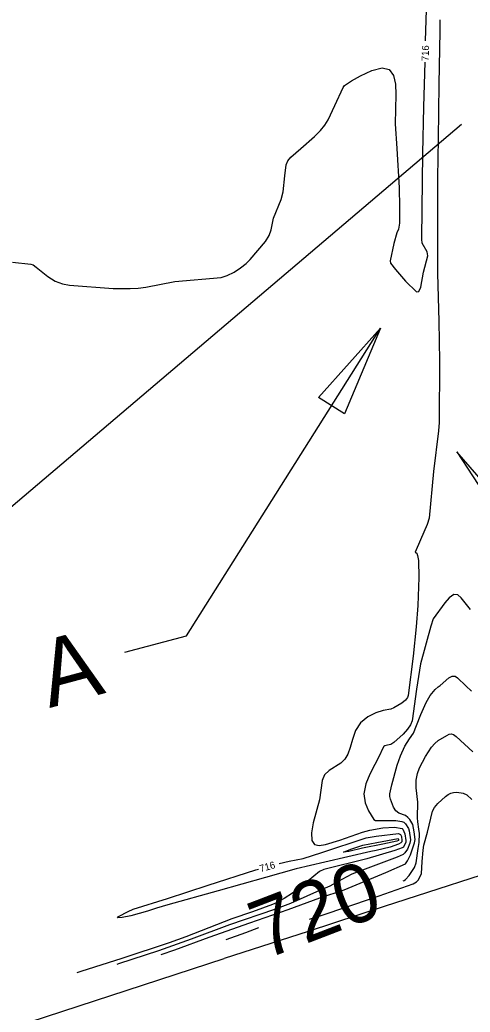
# Model space of a CAD drawing. Extents: x -361782338 to 28259792, y -263199453 to 8342113.
# Drawn here: x 1403593 to 1403847, y 576353 to 576912 of the extents above; entities that cross this region are included whole.
import ezdxf

# ---------------------------------------------------------------- set-up
doc = ezdxf.new("R2010")
doc.units = 0
for name, color, linetype in [('DT_X_Contour_Minor', 7, 'Continuous'), ('Level 14', 7, 'Continuous'), ('Level 19', 7, 'Continuous'), ('Level 40', 7, 'Continuous')]:
    doc.layers.add(name, color=color, linetype=linetype)

msp = doc.modelspace()

# ---------------------------------------------------------------- linework, layer by layer
at = {"layer": 'DT_X_Contour_Minor'}
for points in [[(1403821.78, 576911.42), (1403822.06, 576923.26)], [(1403829.55, 576911.53), (1403829.49, 576905.1), (1403829.01, 576875.26), (1403828.59, 576844.44), (1403828.19, 576822.78), (1403828.15, 576791.45), (1403828.18, 576768.59), (1403828.92, 576741.81), (1403829.26, 576719.37), (1403829.07, 576684.77), (1403828.78, 576680.05), (1403825.88, 576657.2), (1403823.4, 576630.94), (1403822.35, 576627.29), (1403818.6, 576618.64), (1403815.5, 576611.83), (1403816.42, 576611.11), (1403816.98, 576609.82), (1403817.41, 576607.14), (1403817.57, 576597.56), (1403817.02, 576581.73), (1403816.16, 576569.64), (1403814.48, 576553.18), (1403811.65, 576531.01), (1403811.17, 576529.81), (1403810.04, 576528.37), (1403808.09, 576526.73), (1403803.54, 576523.99), (1403801.86, 576523.41), (1403797.46, 576522.48), (1403793.45, 576521.21), (1403788.84, 576519.02), (1403784.75, 576515.71), (1403781.99, 576511.26), (1403780.27, 576506.31), (1403779.01, 576501.66), (1403777.69, 576497.95), (1403775.97, 576495.09), (1403773.58, 576492.83), (1403767.13, 576488.86), (1403764.5, 576486.35), (1403763.11, 576483.09), (1403761.57, 576472.34), (1403758.03, 576459.23), (1403757.14, 576453.77), (1403757.24, 576449.43), (1403758.74, 576447.15), (1403761.43, 576446.6), (1403764.93, 576447.14), (1403773.14, 576449.58), (1403785.89, 576454.09), (1403789.93, 576455.23), (1403797.25, 576456.44), (1403804, 576456.78), (1403808.3, 576456.14), (1403808.69, 576455.67), (1403809.72, 576453.15), (1403810.37, 576449.42), (1403810.29, 576448.36), (1403808.97, 576445.6), (1403808.28, 576445.18), (1403804.02, 576443.74), (1403788.36, 576439.08), (1403764.06, 576433.08), (1403761.63, 576431.9), (1403755.15, 576426.7), (1403746.41, 576419.75), (1403741.67, 576416.76), (1403739.7, 576415.55), (1403738.2, 576414.63), (1403735.11, 576413.24), (1403723.82, 576409.21), (1403712.18, 576405.2), (1403686.33, 576395.18), (1403676.92, 576391.74), (1403650.21, 576382.96), (1403626.98, 576375.57), (1403624.87, 576374.87)], [(1403821.46, 576899.62), (1403821.75, 576911.41)], [(1403742.82, 576829.82), (1403743.76, 576832.12), (1403745.44, 576834.22), (1403751.06, 576839.03), (1403758.72, 576845.78), (1403762.13, 576849.19), (1403764.63, 576852.23), (1403766.54, 576855.27), (1403770.31, 576863.26), (1403774.95, 576873.37), (1403775.8, 576874.59), (1403776.81, 576875.38), (1403779.62, 576877.17), (1403784.76, 576880.08), (1403791.05, 576883.01), (1403796.87, 576884.51), (1403800.94, 576883.5), (1403803.32, 576880.25), (1403804.44, 576875.39), (1403804.7, 576869.56), (1403804.24, 576852.97), (1403805.23, 576839.06), (1403806.58, 576816.91), (1403806.81, 576806), (1403806.67, 576797.08), (1403806.23, 576793.73), (1403805.2, 576791.5), (1403803.62, 576785.57), (1403801.45, 576775.81), (1403801.66, 576774.56), (1403804.4, 576771.02), (1403810.18, 576764.42), (1403816.23, 576758.33), (1403817.72, 576758.48), (1403818.71, 576761.02), (1403820.26, 576769.5), (1403822.8, 576778.71), (1403822.28, 576780.83), (1403819.55, 576785.8), (1403819.31, 576788.06), (1403819.5, 576805.17), (1403819.86, 576836.27), (1403820.46, 576862.46), (1403821.16, 576887.62)], [(1403588.46, 576775), (1403598.89, 576774.01), (1403600.13, 576773.56), (1403601.9, 576772.26), (1403608.4, 576766.9), (1403612.49, 576764.36), (1403616.65, 576762.84), (1403620.75, 576762.13), (1403645.35, 576760.32), (1403654.8, 576760.23), (1403659.43, 576760.5), (1403663.78, 576761.03), (1403680.13, 576764.11), (1403706.17, 576766.47), (1403709.63, 576767.53), (1403713.42, 576769.44), (1403717.14, 576771.88), (1403720.27, 576774.37), (1403722.5, 576776.57), (1403731.21, 576786.75), (1403733.27, 576790.02), (1403734.37, 576793.33), (1403735.62, 576799.87), (1403740, 576810.3), (1403741.05, 576814.74), (1403742.09, 576823.61), (1403742.82, 576829.82)], [(1403846.72, 576579.41), (1403841.51, 576586.1), (1403839.62, 576587.67), (1403837.39, 576587.86), (1403834.82, 576586.11), (1403832.31, 576583.29), (1403825.75, 576574.28), (1403824.41, 576570.11), (1403818.51, 576548.85), (1403816.33, 576534.65), (1403813.79, 576516.72), (1403812.92, 576514.5), (1403811.33, 576512.04), (1403808.86, 576509.27), (1403803.5, 576504.52), (1403801.79, 576503.47), (1403799.92, 576503.1), (1403798.42, 576502.69), (1403797.83, 576502.22), (1403797.05, 576500.63), (1403795.67, 576497.56), (1403789.98, 576486.76), (1403787.76, 576481.29), (1403786.72, 576475.68), (1403787.46, 576470.49), (1403789.27, 576466.13), (1403792.25, 576461.27), (1403793.12, 576460.63), (1403796.7, 576460.59), (1403804.62, 576460.57), (1403808.03, 576460.1), (1403809.23, 576459.59), (1403810.21, 576458.75), (1403811.79, 576456.21), (1403812.18, 576454.87), (1403812.9, 576449.71), (1403812.51, 576447.88), (1403811.22, 576444.55), (1403809.71, 576442.34), (1403808.74, 576441.53), (1403805.36, 576440.04), (1403779.78, 576430.43), (1403774.27, 576427.4), (1403767.4, 576423.56), (1403759.98, 576420.38), (1403745.22, 576413.91), (1403736.33, 576410.56), (1403710.95, 576401.9), (1403689.25, 576393.76), (1403670.8, 576387.15), (1403648.35, 576379.82), (1403647.43, 576379.54)], [(1403672.34, 576385.2), (1403680.11, 576387.85), (1403699.43, 576394.86), (1403722.28, 576403.01), (1403744.02, 576410.52), (1403761.83, 576417.08), (1403775.53, 576421.66), (1403799.03, 576431.34), (1403810.06, 576436.31), (1403811.2, 576437.87), (1403812.95, 576441.28), (1403815.21, 576448.09), (1403815.56, 576449.96), (1403815.06, 576454.31), (1403814.26, 576458.29), (1403812.48, 576461.16), (1403811.5, 576462.36), (1403810.14, 576463.39), (1403806.4, 576464.82), (1403804.63, 576466.07), (1403803.28, 576468.13), (1403801.73, 576472.71), (1403801.38, 576474.2), (1403801.34, 576475.57), (1403802.45, 576480.79), (1403805.4, 576491.71), (1403807.21, 576497.05), (1403809.67, 576502.42), (1403812.39, 576506.61), (1403814.69, 576509.79), (1403816.37, 576514.04), (1403818.73, 576520.33), (1403821.74, 576527.01), (1403824.05, 576531.11), (1403826.77, 576534.43), (1403828.51, 576535.97), (1403829.58, 576536.74), (1403834.53, 576540.98), (1403836.48, 576541.98), (1403838.06, 576541.89), (1403839.43, 576540.92), (1403844.13, 576536.5), (1403847.36, 576533.45)], [(1403808.84, 576426.62), (1403809.32, 576426.86), (1403810.15, 576427.39), (1403812.17, 576429.67), (1403815.21, 576434.24), (1403816.07, 576436.71), (1403817.31, 576444.81), (1403817.86, 576448.26), (1403818.07, 576453.34), (1403817.71, 576455.79), (1403817, 576459.78), (1403816.83, 576462.21), (1403817.03, 576470.96), (1403816.12, 576479.09), (1403816.09, 576483.26), (1403816.81, 576487.04), (1403818.04, 576490.32), (1403821.39, 576496.74), (1403824.7, 576501.93), (1403826.6, 576504.08), (1403828.63, 576505.7), (1403833.43, 576508.5), (1403834.75, 576509.2), (1403835.95, 576509.48), (1403837.23, 576509.12), (1403838.76, 576507.99), (1403848.06, 576499.21)], [(1403756.06, 576405.11), (1403762.5, 576407.16), (1403792.15, 576416.98), (1403814.42, 576424.94), (1403816.36, 576426.06), (1403817.24, 576426.97), (1403819.05, 576430.65), (1403819.48, 576437.56), (1403820.02, 576443.96), (1403820.54, 576446.73), (1403822.57, 576454.06), (1403825.36, 576465.85), (1403826.5, 576467.85), (1403828.42, 576470.11), (1403832.67, 576474.16), (1403834.15, 576475.27), (1403835.63, 576476.04), (1403837.27, 576476.47), (1403839.13, 576476.55), (1403842.66, 576475.97), (1403844.68, 576475.03), (1403847.54, 576472.53)], [(1403738.84, 576436.36), (1403744.57, 576437.69), (1403752.5, 576439.24), (1403762.99, 576442.53), (1403788.02, 576450.94), (1403793.67, 576451.79), (1403806.19, 576453.28), (1403807.32, 576452.65), (1403807.83, 576451.55), (1403808.14, 576449.32), (1403807.98, 576448.64), (1403807.41, 576447.98), (1403806.18, 576447.28), (1403801.5, 576445.69), (1403793.6, 576443.77), (1403790.58, 576443.16), (1403764.7, 576437.11), (1403748.45, 576433.34), (1403731.22, 576428.55), (1403704.4, 576420.94), (1403676.04, 576413.13), (1403669.7, 576411.26), (1403664.67, 576409.54), (1403655.17, 576407), (1403650.35, 576406.01), (1403647.67, 576405.79), (1403648.25, 576406.63), (1403653.72, 576409.39), (1403656.63, 576410.63), (1403676.01, 576416.75), (1403698.91, 576424.19), (1403725.73, 576432.77), (1403727.26, 576433.2)], [(1403785.82, 576444.97), (1403778.1, 576443.23), (1403775.1, 576442.86), (1403779.21, 576444.5), (1403785.97, 576446.69), (1403793.93, 576448.2), (1403805.99, 576450.42), (1403806.23, 576449.96), (1403806.1, 576449.35), (1403805.3, 576449.02), (1403797.38, 576447.3), (1403785.82, 576444.97)], [(1403709.02, 576393.6), (1403720.09, 576397.51), (1403727.5, 576400.37)]]:
    msp.add_lwpolyline(points, dxfattribs=at)
at = {"layer": 'Level 14'}
msp.add_line((1401168.4, 575558.39), (1403707.95, 576382.82), dxfattribs=at)
msp.add_lwpolyline([(1404171.22, 576533.92), (1404124.32, 576518.59), (1404074.79, 576502.42), (1404030.68, 576487.94), (1403976.28, 576470.16), (1403927.93, 576454.25), (1403877.13, 576437.7), (1403798.15, 576412.11), (1403755.23, 576398.08), (1403707.95, 576382.82)], dxfattribs=at)
at = {"layer": 'Level 40'}
for p, q in [((1403841.61, 576852.64), (1403205.9, 576313.06)), ((1403686.55, 576564.62), (1403795.96, 576737.84)), ((1403761.14, 576698.83), (1403795.96, 576737.84)), ((1403795.96, 576737.84), (1403775.66, 576689.65)), ((1403775.66, 576689.65), (1403761.14, 576698.83)), ((1403651.95, 576555.35), (1403686.55, 576564.62))]:
    msp.add_line(p, q, dxfattribs=at)
msp.add_lwpolyline([(1404224.44, 576225.83), (1403839.07, 576668.32), (1404142.69, 576203.92)], close=True, dxfattribs=at)

# ---------------------------------------------------------------- texts
at = {"layer": 'Level 19'}
for s, height, rotation, p in [('716', 4, 88.6251, (1403823.19, 576888.22)), ('720', 33, 21.0046, (1403730.51, 576382.07)), ('716', 4, 15.8595, (1403728.42, 576431.45))]:
    msp.add_text(s, height=height, rotation=rotation, dxfattribs=at).set_placement(p)
at = {"layer": 'Level 40'}
msp.add_text('36" A', height=37.5, rotation=15, dxfattribs=at).set_placement((1403524.79, 576501.27))

doc.saveas('drawing.dxf')
